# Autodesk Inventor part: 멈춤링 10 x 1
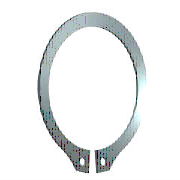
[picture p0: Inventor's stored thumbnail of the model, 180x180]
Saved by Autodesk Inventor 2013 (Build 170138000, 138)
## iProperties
IsCustomPart: 0
Created: 2015-11
Part Number: 멈춤링 10 x 1
Material: 스테인리스강
Description: 리테이닝 링(C형)
Document SubType Name: Modeling
Standard: KS B 1336
Designer: mdu
Standards Organization: KS
Language: ko-KR
Size Designation: 10 x 1
Categories: <MemberInstance><Categories><Category DisplayName="샤프트 부품" InternalName="7f7aeb1f-a693-4053-b835-cee3144e0d98" Mnemonic="SHFT"><Category DisplayName="써클립" Inter
Density: 1 g/cm^3
Author: mdu
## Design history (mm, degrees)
sketch "스케치1"
  geometry: L1 (-6, 0)-(6, 0) reference; L2 (0, 20.189)-(0, -80.536) reference; L3 (-48.09, 0)-(48.09, 0) reference; L4 (-0.3, -9.791)-(-0.3, -12.791); L5 (-0.3, -6.54)-(-0.3, -13.29); L6 (-2.795, 1.6)-(3.672, 1.6); L7 (0.3, -6.54)-(0.3, -13.29); L8 (0.3, -9.791)-(0.3, -12.791); C1 r 0.6 at (-1.2, -11.486); C2 r 0.6 at (1.2, -11.486); A1 r 4.8 centre (0, -5) between (0.3, -9.791) and (-0.3, -9.791); A2 r 6.2 centre (0, -4.6) between (2.988, -10.033) and (-2.988, -10.033); A3 r 7.796 centre (0, -5) between (-1.418, -12.666) and (-0.3, -12.791); A4 r 1.2 centre (-1.2, -11.486) between (-2.383, -11.285) and (-1.418, -12.666); A5 r 1.2 centre (-3.566, -11.084) between (-2.383, -11.285) and (-2.988, -10.033); A6 r 1.2 centre (3.566, -11.084) between (2.988, -10.033) and (2.383, -11.285); A7 r 1.2 centre (1.2, -11.486) between (1.418, -12.666) and (2.383, -11.285); A8 r 7.796 centre (0, -5) between (0.3, -12.791) and (1.418, -12.666)
  constraints: 16 point on circle, 12 end point, 10 centre point, 9 symmetric about line, 5 point on line, 4 tangent, 3 coincident, 2 horizontal, 1 perpendicular, 1 vertical, 5 other
  dimensions: "d0" = 9.6 diameter of A1 (= ND); "d1" = 3 distance of L4.end L4.start (= SRB2); "d6" = 0.3 distance between parallel lines of L2 L5 (= 0.25 x SD5); "d7" = 1.6 distance between parallel lines of L6 L3 (= SRB1); "d8" = 0.4 distance of A1.centre A2.centre (= 0.25 x SRB1); "d9" = 1.2 radius of A4 (= SD5); "d10" = 1.2 radius of A5 (= SD5); "d11" = 0.9 distance from line of L4 A4.centre (= 0.75 x SD5); "d12" = 1.2 diameter of C1 (= SD5); "d13" = 1.2 diameter of C2 (= SD5); "d14" = 5 distance from line of A1.centre L1 (= 0.5 x WD)
extrude "본체" new body sketch "스케치1" distance "d2" = 1 (= SD); taper "d3" = 0 deg
workaxis "Work Axis1"
workplane "Work Plane1"
body "Solid1"
other parameters: "SD" = 1 [user parameter; used in 1 equation term], "SRB1" = 1.6 [user parameter; used in 2 equation terms], "ND" = 9.6 [user parameter; used in 1 equation term], "SRB2" = 3 [user parameter; used in 1 equation term], "SD5" = 1.2 [user parameter; used in 6 equation terms], "d15" = 0, "d16" = 0, "d17" = 0, "d41" = 0, "d42" = 0, "SD3" = 9.3 [user parameter], "WDMAX" = 11 [user parameter]
